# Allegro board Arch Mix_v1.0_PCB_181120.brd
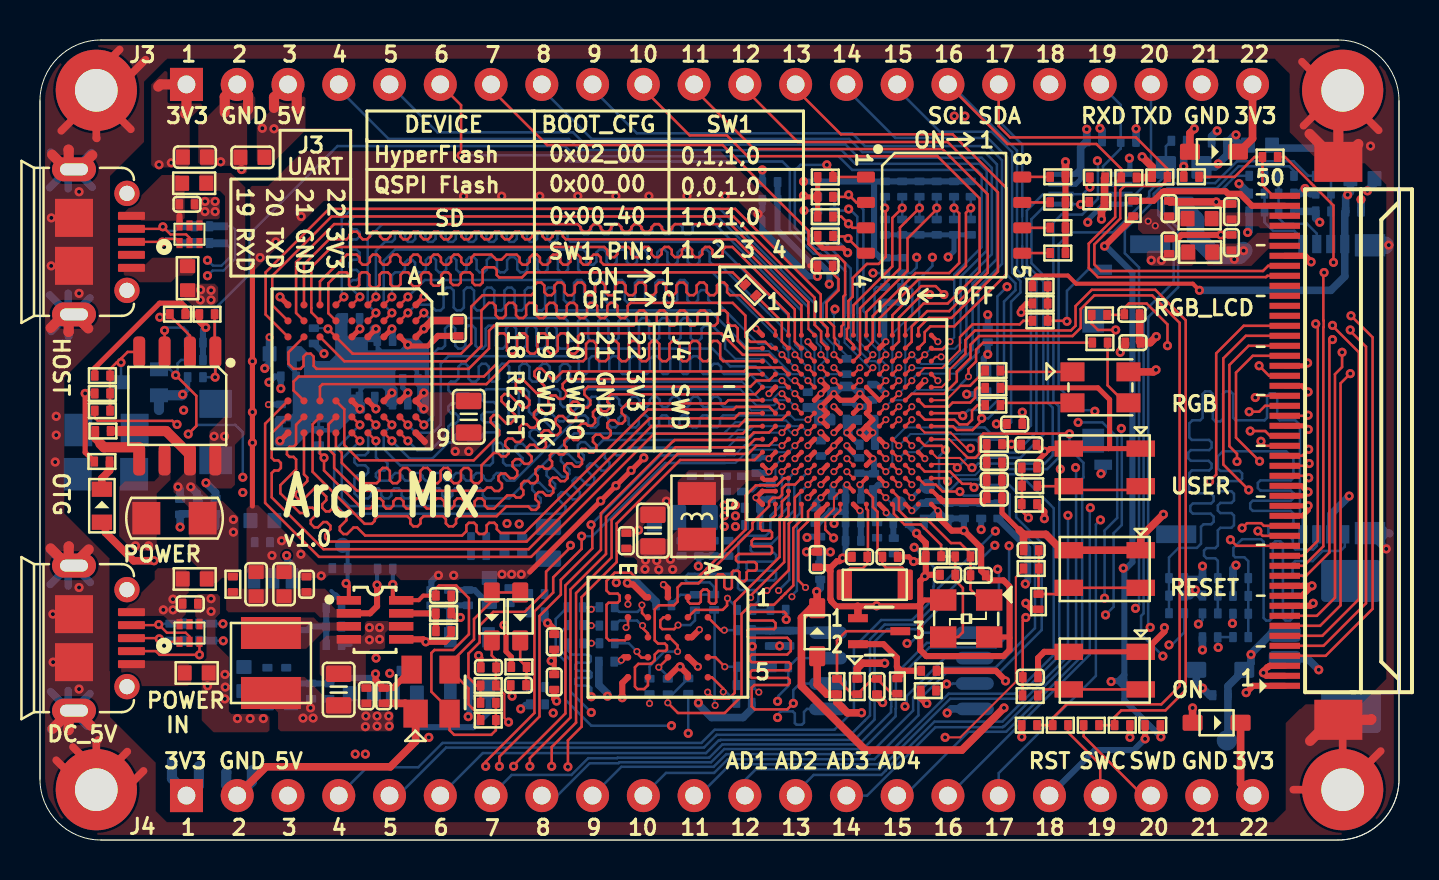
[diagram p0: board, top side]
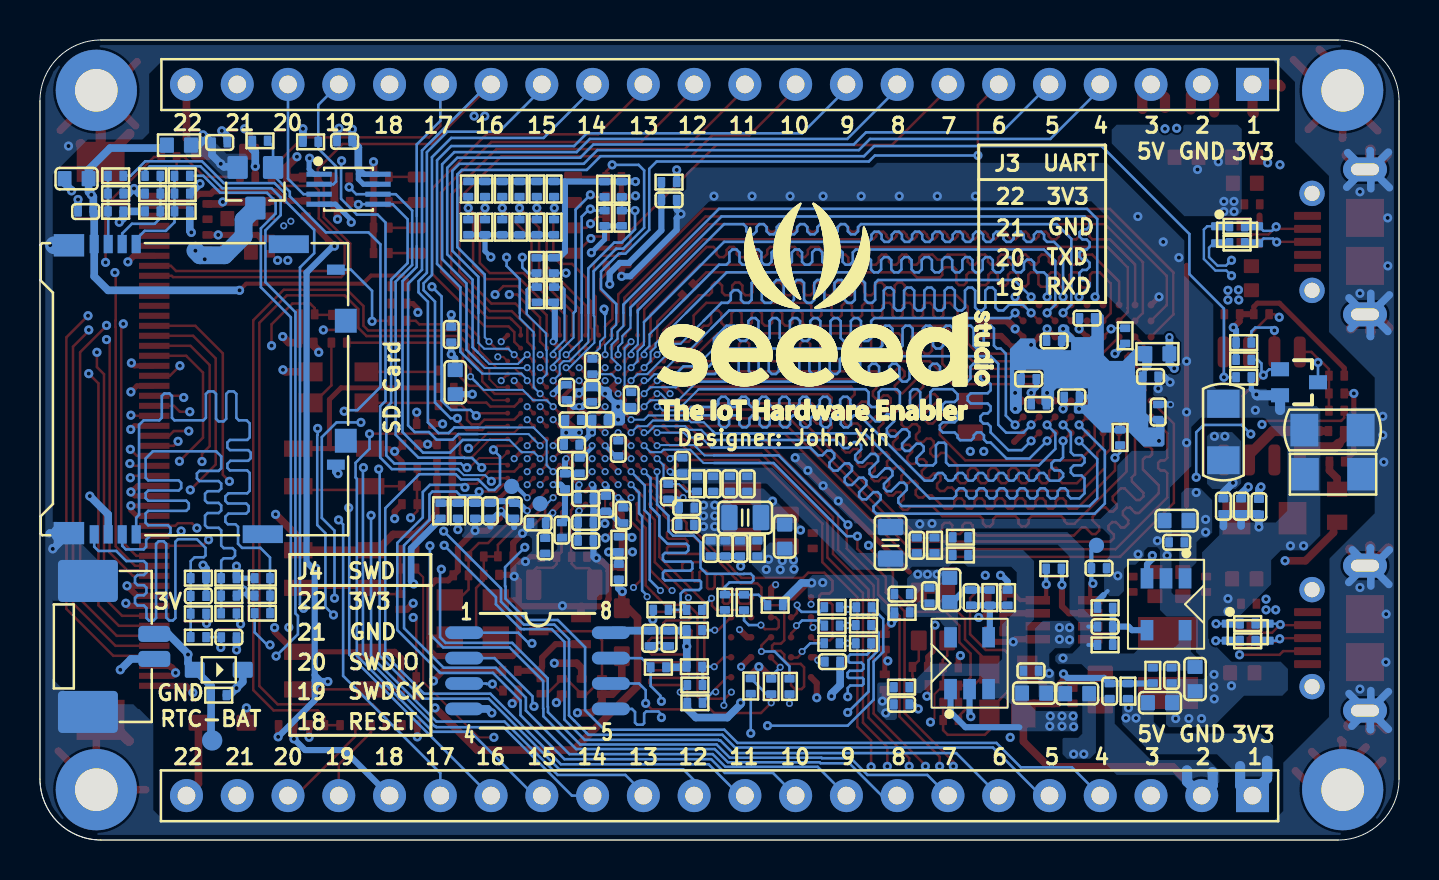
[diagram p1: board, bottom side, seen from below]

Outline 68 x 40 mm; copper layers: TOP, GND02, LYR03, PWR04, GND05, BOTTOM. Coordinates in mm from the lower left corner of the outline.
Outline path: 0,36.95 0,3.05 ; 0,36.95 arc(0.89,39.11) 3.05,40 ; 0,36.95 0,3.05 ; 0,3.05 arc(0.89,0.89) 3.05,0 ; 3.05,40 64.95,40 ; 3.05,40 64.95,40 ; 64.95,40 arc(67.11,39.11) 68,36.95 ; 3.05,0 64.95,0 ; 3.05,0 64.95,0 ; 64.95,0 arc(67.11,0.89) 68,3.05 ; 64.95,0 arc(67.11,0.89) 68,3.05 ; 68,36.95 68,3.05 ; 68,36.95 68,3.05

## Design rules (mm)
constraint set DEFAULT: min track width 0.102
net group DIFFPAIR7: nets USB_OTG_DN USB_OTG_DP
net group LCD_BL_PWM: nets LCD_BL_PWM N1454429
net group OTG2: nets USB_OTG2_DN USB_OTG2_DP
net group OTG3: nets USB_OTG1_DN USB_OTG1_DP
net group SEMC: nets SDRAM_CLK SEMC_DQS
net group ENET: nets ENET_CRS_DV ENET_MDC ENET_MDIO ENET_RXD0 ENET_RXD1 ENET_RXER ENET_TX_CLK ENET_TXD0 ENET_TXD1 ENET_TXEN
net group HF: nets HF_CLK HF_D0_A HF_D1_A HF_D2_A HF_D3_A HF_DQS HF_SS0
net group I2S: nets SAI1_MCLK SAI1_RX_BCLK SAI1_RX_SYNC SAI1_RXD/AD1_Y- SAI1_TX_BCLK/AD3_X- SAI1_TX_SYNC/AD4_X+ SAI1_TXD/AD2_Y+
net group LCD: nets LCD_CLK LCD_PWREN LCDIF_CLK LCDIF_D12 LCDIF_ENABLE LCDIF_HSYNC LCDIF_VSYNC
net group LCD_DATA: nets LCDIF_D0 LCDIF_D1 LCDIF_D2 LCDIF_D3 LCDIF_D4 LCDIF_D5 LCDIF_D6 LCDIF_D7 LCDIF_D8 LCDIF_D9 LCDIF_D10 LCDIF_D11 LCDIF_D13 LCDIF_D14 LCDIF_D15
net group POWER: nets VDD_USB_3V VDDA_1V1_CAP VDDA_2V5_CAP
net group QF: nets QF_CLK QF_D0_A QF_D1_A QF_D2_A QF_D3_A QF_SS0
net group SD: nets SD1_CLK SD1_CMD SD1_D0 SD1_D1 SD1_D2 SD1_D3 SD_CD SD_CD_SW SD_CLK SD_CMD SD_DAT0 SD_DAT1 SD_DAT2 SD_DAT3
net group SEMC_ADD: nets SEMC_CLK
net group SPI: nets FLEXSPI_CLK FLEXSPI_CLK_B FLEXSPI_D0_A FLEXSPI_D0_B FLEXSPI_D1_A FLEXSPI_D1_B FLEXSPI_D2_A FLEXSPI_D2_B FLEXSPI_D3_A FLEXSPI_D3_B FLEXSPI_DQS FLEXSPI_SS0

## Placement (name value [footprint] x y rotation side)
C1  22uF  [C1206]  6.73 16.09 180 top
C2  100nF  [C0402]  7.35 31.79 0 top
C3  100nF  [C0402]  7.52 11.81 0 top
C4  10uF  [C0603]  7.75 34.14 0 top
C5  10uF  [C0603]  10.63 34.13 180 top
C6  10uF  [C0603]  10.82 12.79 90 top
C7  10uF  [C0603]  12.21 12.79 90 top
C8  100nF  [C0402]  13.34 12.79 90 top
C9  22uF  [C0805]  14.95 7.52 90 top
C10  100nF  [C0402]  16.33 7.22 90 top
C11  100nF  [C0402]  17.2 7.22 270 top
C12  220nF  [C0402]  20.19 12.22 0 top
C13  100nF  [C0402]  20.94 25.59 90 top
C14  22uF  [C0805]  21.45 21.16 270 top
C15  1nF  [C0402]  22.44 8.63 180 top
C16  1uF  [C0402]  23.94 7.74 0 top
C17  4.7uF  [C0402]  25.73 9.91 270 top
C18  100nF  [C0402]  25.73 7.9 90 top
C19  220nF  [C0402]  29.34 14.96 90 top
C20  22uF  [C0805]  30.67 15.47 90 top
C21  1uF  [C0402]  38.89 14.02 270 top
C22  100nF  [C0402]  39.28 28.71 180 top
C23  24pF  [C0402]  41.01 14.16 180 top
C24  100nF  [C0402]  41.88 7.67 270 top
C25  24pF  [C0402]  42.53 14.16 0 top
C26  4.7pF  [C0402]  45.42 13.26 180 top
C27  4.7pF  [C0402]  46.94 13.23 0 top
C28  100nF  [C0402]  47.75 18.87 0 top
C29  1uF  [C0402]  47.75 17.98 0 top
C30  220nF  [C0402]  47.75 17.1 0 top
C31  100nF  [C0402]  48.77 20.8 0 top
C32  100nF  [C0402]  49.48 19.76 0 top
C33  1uF  [C0402]  49.5 18.62 0 top
C34  1uF  [C0402]  49.56 8.14 0 top
C35  1uF  [C0402]  49.59 14.49 180 top
C36  10pF  [C0402]  54.64 26.28 0 top
C37  4.7uF  [C0402]  54.69 24.87 0 top
C38  1uF  [C0402]  56.49 31.57 90 top
C39  1uF  [C0402]  56.49 29.69 90 top
C40  1uF  [C0402]  59.62 31.42 90 top
C41  1uF  [C0402]  59.62 29.87 90 top
C42  10uF  [C0603]  66.17 33.07 0 bottom
C43  100nF  [C0402]  65.71 31.42 0 bottom
C44  18pF  [C0402]  60.07 12.2 180 bottom
C45  100nF  [C0402]  59.01 34.88 180 bottom
C46  100nF  [C0402]  52.76 34.93 0 bottom
C47  100nF  [C0402]  47.42 25.27 270 bottom
C48  10uF  [C0603]  47.22 22.89 90 bottom
C49  4.7uF  [C0402]  46.23 16.46 270 bottom
C50  220nF  [C0402]  45.47 16.46 270 bottom
C51  100nF  [C0402]  44.27 16.46 270 bottom
C52  220nF  [C0402]  43.08 15.85 0 bottom
C53  4.7uF  [C0402]  42.72 14.71 270 bottom
C54  220nF  [C0402]  41.73 17.93 90 bottom
C55  4.7uF  [C0402]  41.88 15.5 270 bottom
C56  4.7uF  [C0402]  41.64 22.39 270 bottom
C57  220nF  [C0402]  41.4 19.76 180 bottom
C58  220nF  [C0402]  41.33 21.01 180 bottom
C59  100nF  [C0402]  41 18.72 270 bottom
C60  220nF  [C0402]  40.69 17.07 180 bottom
C61  4.7uF  [C0402]  40.69 15.88 180 bottom
C62  220nF  [C0402]  40.69 14.96 180 bottom
C63  220nF  [C0402]  40.37 22.29 270 bottom
C64  100nF  [C0402]  40.36 23.67 90 bottom
C65  220nF  [C0402]  39.97 21.02 0 bottom
C66  100nF  [C0402]  39.67 16.82 270 bottom
C67  100nF  [C0402]  39.07 19.58 270 bottom
C68  1uF  [C0402]  38.81 16.23 270 bottom
C69  4.7uF  [C0402]  38.42 22.01 90 bottom
C70  100nF  [C0402]  37.49 10.09 270 bottom
C71  220nF  [C0402]  36.56 17.42 270 bottom
C72  4.7uF  [C0402]  36.53 32.01 180 bottom
C73  1uF  [C0402]  36.53 10.09 270 bottom
C74  220nF  [C0402]  35.85 18.73 90 bottom
C75  220nF  [C0402]  35.66 15.75 0 bottom
C76  220nF  [C0402]  35.64 16.61 0 bottom
C77  220nF  [C0402]  34.44 14.58 270 bottom
C78  4.7uF  [C0402]  34.32 17.81 270 bottom
C79  220nF  [C0402]  33.71 14.58 270 bottom
C80  220nF  [C0402]  33.48 17.81 270 bottom
C81  220nF  [C0402]  32.97 14.58 270 bottom
C82  22uF  [C0805]  32.72 16.12 180 bottom
C83  220nF  [C0402]  32.61 17.81 270 bottom
C84  10uF  [C0603]  30.74 15.17 90 bottom
C85  100nF  [C0402]  28.35 8.92 180 bottom
C86  22uF  [C0805]  25.44 14.86 90 bottom
C87  100nF  [C0402]  24.89 6.78 180 bottom
C88  4.7uF  [C0402]  24.87 12.3 180 bottom
C89  100nF  [C0402]  24.13 14.73 90 bottom
C90  100nF  [C0402]  23.5 12.22 90 bottom
C91  10uF  [C0603]  22.48 12.5 90 bottom
C92  1nF  [C0402]  21.41 12.12 270 bottom
C93  100nF  [C0402]  18.53 23.05 180 bottom
C94  100nF  [C0402]  18.41 8.46 180 bottom
C95  10uF  [C0603]  18.26 7.35 180 bottom
C96  100nF  [C0402]  18.02 21.78 0 bottom
C97  100nF  [C0402]  17.26 24.95 0 bottom
C98  4.7uF  [C0402]  16.37 22.16 0 bottom
C99  10uF  [C0603]  16.1 7.32 0 bottom
C100  100nF  [C0402]  15.61 26.1 0 bottom
C101  1nF  [C0402]  15.01 13.59 180 bottom
C102  390pF  [C0402]  14.71 10.67 180 bottom
C103  100nF  [C0402]  14.48 7.44 270 bottom
C104  100nF  [C0402]  12.43 23.17 180 bottom
C105  10uF  [C0603]  11.96 6.86 180 bottom
C106  100nF  [C0402]  12.05 21.4 90 bottom
C107  100nF  [C0402]  11.38 8.23 270 bottom
C108  10uF  [C0603]  11.13 15.97 0 bottom
C109  100nF  [C0402]  11.13 14.89 0 bottom
C110  10uF  [C0603]  10.21 8.05 270 bottom
C111  22uF  [C1206]  8.79 20.4 90 bottom
C112  100nF  [C0402]  8.79 16.69 270 bottom
C113  100nF  [C0402]  7.9 16.69 270 bottom
C114  100nF  [C0402]  7.01 16.66 270 bottom
C115  1nF  [C1206]  3.33 20.5 0 bottom
C116  18pF  [C0402]  58.55 10.14 180 bottom
D1  PMEG3010CEJ  [SOD_323]  22.61 11.18 270 top
D2  PMEG3010CEJ  [SOD_323]  24.03 11.18 270 top
D3  PMEG3010CEJ  [SOD_323]  38.89 10.39 90 top
D4  ESDPSA0402V05  [D0402]  50.04 26.82 180 top
D5  PMEG3010CEJ  [SOD_323]  58.87 5.86 0 top
D6  PMEG3010CEJ  [SOD_323]  58.74 34.41 0 top
D7  ESDPSA0402V05  [D0402]  64.21 31.43 180 bottom
D8  ESDPSA0402V05  [D0402]  62.36 31.43 0 bottom
D9  ESDPSA0402V05  [D0402]  60.89 31.43 180 bottom
D10  ESDPSA0402V05  [D0402]  60.07 13.09 180 bottom
D11  PMEG3010CEJ  [SOD_323]  59.05 8.51 180 bottom
D12  ESDPSA0402V05  [D0402]  58.55 13.09 180 bottom
D13  ESDPSA0402V05  [D0402]  56.87 13.09 0 bottom
FB1  120R  [L0603]  7.72 32.84 180 top
FB2  120R  [L0603]  7.74 13.05 180 top
FB3  120R  [L0603]  58.02 31.07 0 top
FB4  120R  [L0603]  58.05 29.39 0 top
FB5  120R  [L0603]  61.04 34.74 0 bottom
FB6  120R  [L0603]  12.09 24.31 0 bottom
FB7  120R  [L0603]  7.84 8.35 180 top
FB8  120R  [L0603]  7.39 28.09 90 top
J1  USB-MC-001-05  [MICRO_USB_5_6P_SMD_0D65_AB]  1.7 29.91 270 top
J2  USB-MC-001-05  [MICRO_USB_5_6P_SMD_0D65_AB]  1.7 10.09 270 top
J3  Header 1x22 2.54mm  [HEADER22P_2D54_DIP]  34 37.78 270 bottom
J4  Header 1x22 2.54mm  [HEADER22P_2D54_DIP]  34 2.22 270 bottom
J5  FPC 50Pin Bottom Contact  [FPC50_2P5_T]  62.28 32.21 180 top
J6  Header 1x2 1.25mm  [JST2P_1D25_7_55X3_9MM]  62.28 9.68 270 bottom
J7  SCHA5B0200  [SD-MICRO-SCHA5B0300]  63.19 22.54 270 bottom
L1  1uH  [L4X4MM]  11.56 8.85 270 top
L2  4.7uH  [L1008]  32.87 16.18 270 top
L3  90R  [L2012]  8.1 30.26 180 bottom
L4  90R  [L2012]  7.57 10.39 180 bottom
LED1  Green  [LED0603]  3.1 16.71 90 top
LED2  RGB  [LED350X280-4]  53.06 22.63 0 top
MTG1  MHOLE  [MTGH160C80D_PL]  2.82 37.48 0 top
MTG2  MHOLE  [MTGH160C80D_PL]  2.82 2.52 0 top
MTG3  MHOLE  [MTGH160C80D_PL]  65.18 37.48 0 top
MTG4  MHOLE  [MTGH160C80D_PL]  65.18 2.52 0 top
NOREF  -  []  0 40.59 0 top
NOREF#2  -  []  4.24 0 90 top
NOREF#3  -  []  5.58 13.01 0 top
NOREF#4  -  []  29.38 29.3 180 bottom
Q1  DMP2035U-7  [SOT23]  57.23 32.61 0 bottom
Q2  BSS138W  [SOT-323-3]  5 22.89 270 bottom
R1  1K  [R0402]  3.1 18.92 0 top
R2  10K  [R0402]  3.12 23.22 0 top
R3  10K  [R0402]  3.12 22.33 180 top
R4  0R  [R0402]  3.12 21.46 0 top
R5  0R  [R0402]  3.15 20.45 0 top
R6  10K  [R0402]  6.88 26.29 180 top
R7  10K  [R0402]  8.36 26.29 0 top
R8  0R  [R0402]  9.65 12.79 270 top
R9  40.2K  [R0402]  20.19 11.33 0 top
R10  180K  [R0402]  20.19 10.44 180 top
R11  0R  [R0402]  22.43 7.72 0 top
R12  10K  [R0402]  22.43 6.86 0 top
R13  0R  [R0402]  22.43 6 0 top
R14  1M  [R0402]  23.96 8.65 180 top
R15  33R  [R0402]  35.55 27.49 135 top
R16  10K  [R0402]  39.29 33.15 0 top
R17  10K  [R0402]  39.29 32.16 0 top
R18  10K  [R0402]  39.29 31.17 0 top
R19  10K  [R0402]  39.29 30.2 0 top
R20  1.5K  [R0402]  39.88 7.67 90 top
R21  1.5K  [R0402]  40.89 7.67 270 top
R22  0R  [R0402]  42.9 7.7 90 top
R23  10K  [R0402]  44.45 7.47 0 top
R24  1K  [R0402]  44.48 8.46 0 top
R25  2.2M  [R0402]  44.7 14.18 180 top
R26  1M  [R0402]  46.18 14.17 0 top
R27  1.5K  [R0402]  47.68 23.47 180 top
R28  10K  [R0402]  47.68 22.61 0 top
R29  4.7K  [R0402]  47.68 21.74 180 top
R30  0R  [R0402]  47.75 19.79 180 top
R31  100K  [R0402]  49.5 16.79 180 top
R32  100K  [R0402]  49.5 5.74 180 top
R33  100R  [R0402]  49.52 17.71 180 top
R34  100R  [R0402]  49.54 7.22 180 top
R35  100R  [R0402]  49.59 13.57 180 top
R36  100R  [R0402]  49.96 11.91 270 top
R37  10K  [R0402]  50.04 27.69 0 top
R38  33R  [R0402]  50.04 25.96 0 top
R39  1K  [R0402]  50.93 33.16 180 top
R40  1K  [R0402]  50.93 31.89 180 top
R41  1K  [R0402]  50.93 30.62 180 top
R42  1K  [R0402]  50.93 29.35 180 top
R43  33R  [R0402]  51.05 5.74 0 top
R44  33R  [R0402]  52.6 5.74 180 top
R45  10K  [R0402]  52.88 31.9 180 top
R46  10K  [R0402]  52.91 33.13 180 top
R47  33R  [R0402]  53.01 26.26 0 top
R48  1.5K  [R0402]  53.04 24.87 180 top
R49  100K  [R0402]  54.15 5.74 180 top
R50  4.7K  [R0402]  54.48 33.12 180 top
R51  0R  [R0402]  55.68 5.74 180 top
R52  4.7K  [R0402]  56.03 33.15 0 top
R53  1K  [R0402]  57.61 33.16 180 top
R54  0R  [R0402]  54.7 31.58 90 top
R55  0R  [R0402]  61.55 34.15 180 top
R56  33R  [R0402]  64.21 33.21 0 bottom
R57  10K  [R0402]  64.21 32.32 0 bottom
R58  33R  [R0402]  62.36 33.21 180 bottom
R59  10K  [R0402]  62.36 32.32 180 bottom
R60  33R  [R0402]  60.89 33.21 0 bottom
R61  10K  [R0402]  60.89 32.32 0 bottom
R62  10K  [R0402]  60.07 11.31 0 bottom
R63  33R  [R0402]  60.07 10.15 0 bottom
R64  1K  [R0402]  59.05 7.24 180 bottom
R65  10K  [R0402]  58.55 12.22 0 bottom
R66  33R  [R0402]  58.55 11.33 0 bottom
R67  10K  [R0402]  56.99 34.96 0 bottom
R68  10K  [R0402]  56.87 12.22 180 bottom
R69  33R  [R0402]  56.87 11.34 180 bottom
R70  100K  [R0402]  54.46 34.91 0 bottom
R71  0R  [R0402]  47.96 16.46 90 bottom
R72  0R  [R0402]  47.09 16.46 90 bottom
R73  1K  [R0402]  46.57 32.55 270 bottom
R74  10K  [R0402]  46.57 30.64 90 bottom
R75  1K  [R0402]  45.73 32.55 270 bottom
R76  10K  [R0402]  45.73 30.64 90 bottom
R77  1K  [R0402]  44.87 32.55 270 bottom
R78  10K  [R0402]  44.87 30.64 90 bottom
R79  1K  [R0402]  44.01 32.55 270 bottom
R80  10K  [R0402]  44.01 30.64 90 bottom
R81  1K  [R0402]  43.15 28.73 270 bottom
R82  1K  [R0402]  43.14 32.55 270 bottom
R83  10K  [R0402]  43.14 30.64 90 bottom
R84  10K  [R0402]  43.14 27.26 90 bottom
R85  1K  [R0402]  42.29 28.73 270 bottom
R86  1K  [R0402]  42.28 32.55 270 bottom
R87  10K  [R0402]  42.28 30.64 90 bottom
R88  10K  [R0402]  42.28 27.26 90 bottom
R89  1K  [R0402]  39.75 32.54 270 bottom
R90  10K  [R0402]  39.75 31.09 90 bottom
R91  100K  [R0402]  39.04 14.78 90 bottom
R92  100R  [R0402]  39.04 13.41 90 bottom
R93  1K  [R0402]  38.89 32.54 270 bottom
R94  10K  [R0402]  38.89 31.09 90 bottom
R95  10K  [R0402]  37.06 8.64 0 bottom
R96  33R  [R0402]  36.93 11.51 0 bottom
R97  0R  [R0402]  36.53 32.89 0 bottom
R98  0R  [R0402]  35.27 11.5 180 bottom
R99  10K  [R0402]  35.26 10.49 180 bottom
R100  10K  [R0402]  35.26 8.66 180 bottom
R101  0R  [R0402]  35.23 7.75 180 bottom
R102  10K  [R0402]  35.23 6.86 180 bottom
R103  30K  [R0402]  35.13 17.81 90 bottom
R104  0R  [R0402]  33.73 11.89 270 bottom
R105  0R  [R0402]  32.77 11.88 270 bottom
R106  0R  [R0402]  32.44 7.7 90 bottom
R107  0R  [R0402]  32.11 14.58 270 bottom
R108  0R  [R0402]  31.41 7.68 90 bottom
R109  10K  [R0402]  31.22 11.74 0 bottom
R110  0R  [R0402]  30.5 7.68 90 bottom
R111  0R  [R0402]  28.38 9.84 0 bottom
R112  0R  [R0402]  28.37 11.64 0 bottom
R113  0R  [R0402]  28.37 10.72 0 bottom
R114  0R  [R0402]  26.8 10.75 0 bottom
R115  0R  [R0402]  26.8 9.83 0 bottom
R116  0R  [R0402]  26.77 11.63 0 bottom
R117  0R  [R0402]  24.89 7.65 0 bottom
R118  0R  [R0402]  24.87 11.38 0 bottom
R119  3.3K  [R0402]  23.24 14.73 90 bottom
R120  0R  [R0402]  21.95 15.14 0 bottom
R121  0R  [R0402]  21.95 14.25 0 bottom
R122  22.6K  [R0402]  20.47 12.12 270 bottom
R123  18K  [R0402]  19.58 12.12 90 bottom
R124  100K  [R0402]  17.27 13.57 0 bottom
R125  18K  [R0402]  14.71 11.61 0 bottom
R126  56.2K  [R0402]  14.71 9.76 180 bottom
R127  100K  [R0402]  13.96 20.13 270 bottom
R128  0R  [R0402]  13.56 7.44 90 bottom
R129  100K  [R0402]  13.7 25.21 270 bottom
R130  0R  [R0402]  12.32 8.23 270 bottom
R131  0R  [R0402]  8.1 30.68 180 bottom
R132  0R  [R0402]  8.1 29.85 180 bottom
R133  10K  [R0402]  7.77 24.87 180 bottom
R134  10K  [R0402]  7.77 24 180 bottom
R135  10K  [R0402]  7.77 23.14 180 bottom
R136  0R  [R0402]  7.57 10.82 180 bottom
R137  0R  [R0402]  7.57 9.96 180 bottom
R138  0R  [R1206]  3.3 18.29 0 bottom
SW1  DIP Switches  [SW8P_1D27_6_21X6_2X2_3MM]  45.24 31.24 0 top
SW2  Tactile Switch  [SW_4P]  53.28 18.63 180 top
SW3  Tactile Switch  [SW_4P]  53.28 13.55 180 top
SW4  Tactile Switch  [SW_4P]  53.28 8.47 180 top
TP1  TP_30MIL  [TESTPOINT_30]  44.4 17.68 180 bottom
TP2  TP_30MIL  [TESTPOINT_30]  42.98 16.82 180 bottom
TP3  TP_30MIL  [TESTPOINT_30]  15.14 14.73 180 bottom
TP4  TP_40MIL  [TP40C_SMD]  59.39 4.98 180 bottom
U1  MIC2026-1YM-TR  [SOIC8_1D27_4_9X3_9MM]  6.87 21.7 180 top
U2  TPD4S012DRYR  [U_6_DRY]  7.48 30.29 0 top
U3  TPD4S012DRYR  [U_6_DRY]  7.48 10.35 0 top
U4  IS42S16160J-6BLI  [VFBGA54_8X8]  15.61 23.56 270 top
U5  MP2161GJ  [TSOT23_8_0D65_2X1MM]  16.76 11.01 0 top
U6  UM805RE  [SOT_143]  19.55 7.42 0 top
U7  S26KS512SDPBHI02  [PBGA24_1_6X8MM]  31.42 10.14 270 top
U8  MIMXRT1052CVL5B  [BGA196_0P65_10X10MM]  40.37 21.02 0 top
U9  MIC803-29D3VC3-TR  [SC-70-3]  41.99 10.44 270 top
U10  SN74LVC2G241DCUR  [U_8_DCU]  52.56 32.54 270 bottom
U11  IS25WP064A-JBLE  [SO8-25X75-200]  43.1 8.46 270 bottom
U12  AP2127K-ADJTRG1  [SOT23-5]  21.49 8.84 180 bottom
U13  AP2127K-ADJTRG1  [SOT23-5]  11.66 11.79 0 bottom
X1  32.768kHz 12.5pF  [X2_SMD_3_2X1_5MM]  41.77 12.76 180 top
X2  24MHz 9pF  [X4-SMD-3_2X2_5X1_0MM]  46.34 11.08 180 top

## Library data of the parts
C1-C116 = CC
D1-D3 D5 D6 D11 = D
D4 D7-D10 D12 D13 = DIODE TVS BI-DIR
FB1-FB8 = FB
J1 J2 = MicroUSB_5+6P
J3 J4 = Header 1x22
J5 = FPC50 For Emb
J6 = Header_2+2P
J7 = MicroSD Card_8P: Tolerance: X; User Part Number: X
L1 L2 = L
L3 L4 = CL
LED1 = Single LED
LED2 = RGB_LED
MTG1-MTG4 = MHOLE
Q1 = PMOS_123
Q2 = NMOS_123: User Part Number: *
R1-R3 R5-R18 R20-R75 R77-R87 R91-R138 = R
R4 R19 R76 R88-R90 = R: signal model: RES_0402_CC_DISCRETE_0.45_MM_47_0
SW1 = DIP Switches_4CH
SW2-SW4 = Tactile Switch_4P
TP1-TP3 = T POINT R: User Part Number: USERPART#; Tolerance: TOLERANCE
TP4 = T POINT R
U1 = MIC2026
U2 U3 = TPD4S012
U4 = SDRAM_BGA54
U5 = MP2161
U6 = UM805_4P
U7 = HyperFlash_FBGA-24
U8 = MIMXRT1052_BGA-196
U9 = MIC803
U10 = SN74LVC2G241
U11 = QPI_8P
U12 U13 = LDO_5P_FB
X1 = XTAL_2P
X2 = XTAL_4P

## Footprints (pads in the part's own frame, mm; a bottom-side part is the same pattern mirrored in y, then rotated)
BGA196_0P65_10X10MM
  round 0.254 smd: A1(-4.225,4.225) A2(-3.575,4.225) A3(-2.925,4.225) A4(-2.275,4.225) A5(-1.625,4.225) A6(-0.975,4.225) A7(-0.325,4.225) A8(0.325,4.225) A9(0.975,4.225) A10(1.625,4.225) A11(2.275,4.225) A12(2.925,4.225) A13(3.575,4.225) A14(4.225,4.225) B1(-4.225,3.575) B2(-3.575,3.575) B3(-2.925,3.575) B4(-2.275,3.575) B5(-1.625,3.575) B6(-0.975,3.575) B7(-0.325,3.575) B8(0.325,3.575) B9(0.975,3.575) B10(1.625,3.575) B11(2.275,3.575) B12(2.925,3.575) B13(3.575,3.575) B14(4.225,3.575) C1(-4.225,2.925) C2(-3.575,2.925) C3(-2.925,2.925) C4(-2.275,2.925) C5(-1.625,2.925) C6(-0.975,2.925) C7(-0.325,2.925) C8(0.325,2.925) C9(0.975,2.925) C10(1.625,2.925) C11(2.275,2.925) C12(2.925,2.925) C13(3.575,2.925) C14(4.225,2.925) D1(-4.225,2.275) D2(-3.575,2.275) D3(-2.925,2.275) D4(-2.275,2.275) D5(-1.625,2.275) D6(-0.975,2.275) D7(-0.325,2.275) D8(0.325,2.275) D9(0.975,2.275) D10(1.625,2.275) D11(2.275,2.275) D12(2.925,2.275) D13(3.575,2.275) D14(4.225,2.275) E1(-4.225,1.625) E2(-3.575,1.625) E3(-2.925,1.625) E4(-2.275,1.625) E5(-1.625,1.625) E6(-0.975,1.625) E7(-0.325,1.625) E8(0.325,1.625) E9(0.975,1.625) E10(1.625,1.625) E11(2.275,1.625) E12(2.925,1.625) E13(3.575,1.625) E14(4.225,1.625) F1(-4.225,0.975) F2(-3.575,0.975) F3(-2.925,0.975) F4(-2.275,0.975) F5(-1.625,0.975) F6(-0.975,0.975) F7(-0.325,0.975) F8(0.325,0.975) F9(0.975,0.975) F10(1.625,0.975) F11(2.275,0.975) F12(2.925,0.975) F13(3.575,0.975) F14(4.225,0.975) G1(-4.225,0.325) G2(-3.575,0.325) G3(-2.925,0.325) G4(-2.275,0.325) G5(-1.625,0.325) G6(-0.975,0.325) G7(-0.325,0.325) G8(0.325,0.325) G9(0.975,0.325) G10(1.625,0.325) G11(2.275,0.325) G12(2.925,0.325) G13(3.575,0.325) G14(4.225,0.325) H1(-4.225,-0.325) H2(-3.575,-0.325) H3(-2.925,-0.325) H4(-2.275,-0.325) H5(-1.625,-0.325) H6(-0.975,-0.325) H7(-0.325,-0.325) H8(0.325,-0.325) H9(0.975,-0.325) H10(1.625,-0.325) H11(2.275,-0.325) H12(2.925,-0.325) H13(3.575,-0.325) H14(4.225,-0.325) J1(-4.225,-0.975) J2(-3.575,-0.975) J3(-2.925,-0.975) J4(-2.275,-0.975) J5(-1.625,-0.975) J6(-0.975,-0.975) J7(-0.325,-0.975) J8(0.325,-0.975) J9(0.975,-0.975) J10(1.625,-0.975) J11(2.275,-0.975) J12(2.925,-0.975) J13(3.575,-0.975) J14(4.225,-0.975) K1(-4.225,-1.625) K2(-3.575,-1.625) K3(-2.925,-1.625) K4(-2.275,-1.625) K5(-1.625,-1.625) K6(-0.975,-1.625) K7(-0.325,-1.625) K8(0.325,-1.625) K9(0.975,-1.625) K10(1.625,-1.625) K11(2.275,-1.625) K12(2.925,-1.625) K13(3.575,-1.625) K14(4.225,-1.625) L1(-4.225,-2.275) L2(-3.575,-2.275) L3(-2.925,-2.275) L4(-2.275,-2.275) L5(-1.625,-2.275) L6(-0.975,-2.275) L7(-0.325,-2.275) L8(0.325,-2.275) L9(0.975,-2.275) L10(1.625,-2.275) L11(2.275,-2.275) L12(2.925,-2.275) L13(3.575,-2.275) L14(4.225,-2.275) M1(-4.225,-2.925) M2(-3.575,-2.925) M3(-2.925,-2.925) M4(-2.275,-2.925) M5(-1.625,-2.925) M6(-0.975,-2.925) M7(-0.325,-2.925) M8(0.325,-2.925) M9(0.975,-2.925) M10(1.625,-2.925) M11(2.275,-2.925) M12(2.925,-2.925) M13(3.575,-2.925) M14(4.225,-2.925) N1(-4.225,-3.575) N2(-3.575,-3.575) N3(-2.925,-3.575) N4(-2.275,-3.575) N5(-1.625,-3.575) N6(-0.975,-3.575) N7(-0.325,-3.575) N8(0.325,-3.575) N9(0.975,-3.575) N10(1.625,-3.575) N11(2.275,-3.575) N12(2.925,-3.575) N13(3.575,-3.575) N14(4.225,-3.575) P1(-4.225,-4.225) P2(-3.575,-4.225) P3(-2.925,-4.225) P4(-2.275,-4.225) P5(-1.625,-4.225) P6(-0.975,-4.225) P7(-0.325,-4.225) P8(0.325,-4.225) P9(0.975,-4.225) P10(1.625,-4.225) P11(2.275,-4.225) P12(2.925,-4.225) P13(3.575,-4.225) P14(4.225,-4.225)
C0402
  rrect 0.385x0.508 smd: 1(-0.383,0) 2(0.383,0)
C0603
  rrect 0.696x0.762 smd: 1(-0.602,0) 2(0.602,0)
C0805
  rrect 0.819x1.27 smd: 1(-0.79,0) 2(0.79,0)
C1206
  rect 1.397x1.626 smd: 1(-1.41,0) 2(1.41,0)
D0402
  rrect 0.385x0.508 smd: 1(-0.383,0) 2(0.383,0)
FPC50_2P5_T
  rect 1.524x0.305 smd: 1(0,24.5) 2(0,24) 3(0,23.5) 4(0,23) 5(0,22.5) 6(0,22) 7(0,21.5) 8(0,21) 9(0,20.5) 10(0,20) 11(0,19.5) 12(0,19) 13(0,18.5) 14(0,18) 15(0,17.5) 16(0,17) 17(0,16.5) 18(0,16) 19(0,15.5) 20(0,15) 21(0,14.5) 22(0,14) 23(0,13.5) 24(0,13) 25(0,12.5) 26(0,12) 27(0,11.5) 28(0,11) 29(0,10.5) 30(0,10) 31(0,9.5) 32(0,9) 33(0,8.5) 34(0,8) 35(0,7.5) 36(0,7) 37(0,6.5) 38(0,6) 39(0,5.5) 40(0,5) 41(0,4.5) 42(0,4) 43(0,3.5) 44(0,3) 45(0,2.5) 46(0,2) 47(0,1.5) 48(0,1) 49(0,0.5) 50(0,0)
  rect 2.4x2 smd: 51(-2.68,26.2) 52(-2.68,-1.7)
HEADER22P_2D54_DIP
  rect 1.651x1.651 hole 0.889: 1(0,26.67)
  round 1.651 hole 0.889: 2(0,24.13) 3(0,21.59) 4(0,19.05) 5(0,16.51) 6(0,13.97) 7(0,11.43) 8(0,8.89) 9(0,6.35) 10(0,3.81) 11(0,1.27) 12(0,-1.27) 13(0,-3.81) 14(0,-6.35) 15(0,-8.89) 16(0,-11.43) 17(0,-13.97) 18(0,-16.51) 19(0,-19.05) 20(0,-21.59) 21(0,-24.13) 22(0,-26.67)
JST2P_1D25_7_55X3_9MM
  rrect 0.8x1.6 smd: 1(-0.625,0) 2(0.625,0)
  rrect 2.1x3 smd: 3(-3.275,-3.319) 4(3.275,-3.319)
L4X4MM
  rect 1.6x3 smd: 1(-1.5,0) 2(1.5,0)
L0603
  rrect 0.696x0.762 smd: 1(-0.602,0) 2(0.602,0)
L1008
  rect 1.143x1.905 smd: 1(-1.143,0) 2(1.143,0)
L2012
  rrect 0.75x0.4 smd: 1(-0.925,0.425) 2(0.925,0.425) 3(0.925,-0.425) 4(-0.925,-0.425)
LED350X280-4
  rect 1.2x0.95 smd: 1(-1.4,0.775) 2(1.4,0.775) 3(1.4,-0.775) 4(-1.4,-0.775)
LED0603
  rect 0.762x1.016 smd: 1(-0.826,0) 2(0.826,0)
MICRO_USB_5_6P_SMD_0D65_AB
  rrect 0.4x1.35 smd: 1(-1.3,2.875) 2(-0.65,2.875) 3(0,2.875) 4(0.65,2.875) 5(1.3,2.875)
  round 1.27 hole 0.762: 6(-2.425,2.65) 7(2.425,2.65)
  oval 1.2x2.2 hole 0.6x1.4: 8(-3.625,0) 9(3.625,0)
  rect 1.9x1.9 smd: 10(-1.2,0) 11(1.2,0)
MTGH160C80D_PL
  round 4.064 hole 2.134: 1(0,0)
PBGA24_1_6X8MM
  round 0.33 smd: A2(-1,2) A3(0,2) A4(1,2) A5(2,2) B1(-2,1) B2(-1,1) B3(0,1) B4(1,1) B5(2,1) C1(-2,0) C2(-1,0) C3(0,0) C4(1,0) C5(2,0) D1(-2,-1) D2(-1,-1) D3(0,-1) D4(1,-1) D5(2,-1) E1(-2,-2) E2(-1,-2) E3(0,-2) E4(1,-2) E5(2,-2)
R0402
  rrect 0.385x0.508 smd: 1(-0.383,0) 2(0.383,0)
R1206
  rect 1.397x1.626 smd: 1(-1.41,0) 2(1.41,0)
SC-70-3
  rect 0.406x0.991 smd: 1(-0.65,-1.06) 2(0.65,-1.06) 3(0,1.06)
SD-MICRO-SCHA5B0300
  rect 0.914x0.457 smd: 1(-7.257,0) 2(-7.257,-0.7) 3(-7.257,-1.4) 4(-7.257,-2.1) 5(7.257,-2.1) 6(7.257,-1.4) 7(7.257,-0.7) 8(7.257,0)
  rect 0.508x0.889 smd: 9(3.775,9.989) 10(-5.975,9.989)
  rect 0.889x2.007 smd: 11(-7.25,7.635) 12(7.25,6.335)
  rect 1.118x1.524 smd: 13(-7.196,-3.365) 14(7.196,-3.365)
  rect 1.194x1.092 smd: 15(-3.425,10.488) 16(2.575,10.488)
SO8-25X75-200
  oval 0.635x1.905 smd: 1(-1.905,-3.67) 2(-0.635,-3.67) 3(0.635,-3.67) 4(1.905,-3.67) 5(1.905,3.67) 6(0.635,3.67) 7(-0.635,3.67) 8(-1.905,3.67)
SOD_323
  rrect 1x0.8 smd: 1(-1.2,0) 2(1.2,0)
SOIC8_1D27_4_9X3_9MM
  rrect 0.6x1.55 smd: 1(-1.905,-2.7) 2(-0.635,-2.7) 3(0.635,-2.7) 4(1.905,-2.7) 5(1.905,2.7) 6(0.635,2.7) 7(-0.635,2.7) 8(-1.905,2.7)
SOT23
  rrect 1.016x1.143 smd: 1(-0.889,-1.016) 2(0.889,-1.016) 3(0,1.016)
SOT23-5
  rect 0.635x1.016 smd: 1(-0.953,-1.295) 2(0,-1.295) 3(0.953,-1.295) 4(0.953,1.295) 5(-0.953,1.295)
SOT-323-3
  rect 0.7x0.9 smd: 1(-0.65,-0.95) 2(0.65,-0.95) 3(0,0.95)
SOT_143
  rect 1.219x1.397 smd: 1(-0.75,-1.1)
  rect 1.016x1.397 smd: 2(0.95,-1.1) 3(0.95,1.1) 4(-0.95,1.1)
SW8P_1D27_6_21X6_2X2_3MM
  rrect 0.9x0.55 smd: 1(-3.91,1.905) 2(-3.91,0.635) 3(-3.91,-0.635) 4(-3.91,-1.905) 5(3.91,-1.905) 6(3.91,-0.635) 7(3.91,0.635) 8(3.91,1.905)
SW_4P
  rect 1.422x0.813 smd: 1(-1.8,-0.94) 2(-1.8,0.94) 3(1.8,-0.94) 4(1.8,0.94)
TESTPOINT_30
  round 0.762 smd: 1(0,0)
TP40C_SMD
  round 1.016 smd: 1(0,0)
TSOT23_8_0D65_2X1MM
  rect 1.219x0.432 smd: 1(-1.31,0.975) 2(-1.31,0.325) 3(-1.31,-0.325) 4(-1.31,-0.975) 5(1.31,-0.975) 6(1.31,-0.325) 7(1.31,0.325) 8(1.31,0.975)
U_6_DRY
  rect 0.305x0.508 smd: 1(-0.5,-0.439) 2(0,-0.439) 3(0.5,-0.439) 4(0.5,0.439) 5(0,0.439) 6(-0.5,0.439)
U_8_DCU
  rect 0.254x1.27 smd: 1(-0.749,-1.473) 2(-0.249,-1.473) 3(0.249,-1.473) 4(0.749,-1.473) 5(0.749,1.473) 6(0.249,1.473) 7(-0.249,1.473) 8(-0.749,1.473)
VFBGA54_8X8
  round 0.356 smd: A1(-3.2,3.2) A2(-2.4,3.2) A3(-1.6,3.2) A7(1.6,3.2) A8(2.4,3.2) A9(3.2,3.2) B1(-3.2,2.4) B2(-2.4,2.4) B3(-1.6,2.4) B7(1.6,2.4) B8(2.4,2.4) B9(3.2,2.4) C1(-3.2,1.6) C2(-2.4,1.6) C3(-1.6,1.6) C7(1.6,1.6) C8(2.4,1.6) C9(3.2,1.6) D1(-3.2,0.8) D2(-2.4,0.8) D3(-1.6,0.8) D7(1.6,0.8) D8(2.4,0.8) D9(3.2,0.8) E1(-3.2,0) E2(-2.4,0) E3(-1.6,0) E7(1.6,0) E8(2.4,0) E9(3.2,0) F1(-3.2,-0.8) F2(-2.4,-0.8) F3(-1.6,-0.8) F7(1.6,-0.8) F8(2.4,-0.8) F9(3.2,-0.8) G1(-3.2,-1.6) G2(-2.4,-1.6) G3(-1.6,-1.6) G7(1.6,-1.6) G8(2.4,-1.6) G9(3.2,-1.6) H1(-3.2,-2.4) H2(-2.4,-2.4) H3(-1.6,-2.4) H7(1.6,-2.4) H8(2.4,-2.4) H9(3.2,-2.4) J1(-3.2,-3.2) J2(-2.4,-3.2) J3(-1.6,-3.2) J7(1.6,-3.2) J8(2.4,-3.2) J9(3.2,-3.2)
X2_SMD_3_2X1_5MM
  rrect 0.762x1.524 smd: 1(-1.524,0) 2(1.524,0)
X4-SMD-3_2X2_5X1_0MM
  rect 1.321x1.067 smd: 1(-1.15,-0.925) 2(1.15,-0.925) 3(1.15,0.925) 4(-1.15,0.925)

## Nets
3V3_LCD: C41.1 FB4.2 J5.45 J5.46 Q1.3
3V3_SD: C42.1 C43.1 FB5.2 J7.4 R37.1 R57.1 R59.1 R61.1 R62.1 R65.1 R68.1
5V_HOST: C2.1 FB1.2 J1.1(VBUS) U2.6(VBUS)
5V_LCD: C40.1 FB3.2 J5.47 J5.48
5V_OTG: C3.1 C5.1 C99.1 FB2.2 J2.1(VBUS) J3.3 J4.3 U3.6(VBUS)
5V_USB_HOST: C21.1 C111.1 C112.1 FB1.1 U1.8 U8.P6
5V_USB_OTG: C1.1 C38.1 C68.1 C108.1 C109.1 C113.1 C114.1 FB2.1 FB3.1 R5.2 R8.1 U1.7 U8.N6 U13.1 U13.3(S\H\D\N\)
GND: C1.2 C2.2 C3.2 C4.2 C5.2 C6.2 C7.2 C8.2 C9.2 C10.2 C11.2 C12.2 C13.2 C14.2 C15.2 C17.2 C18.2 C19.2 C20.2 C21.2 C22.2 C23.2 C24.2 C25.2 C26.2 C27.2 C28.2 C29.2 C30.2 C31.2 C32.2 C33.2 C34.2 C35.2 C36.2 C37.2 C38.2 C39.2 C40.2 C41.2 C42.2 C43.2 C44.2 C45.2 C46.2 C47.2 C48.2 C49.2 C50.2 C51.2 C52.2 C53.2 C54.2 C55.2 C56.2 C57.2 C58.2 C59.2 C60.2 C61.2 C62.2 C63.2 C64.2 C65.2 C66.2 C67.2 C68.2 C69.2 C70.2 C71.2 C72.2 C73.2 C74.2 C75.2 C76.2 C77.2 C78.2 C79.2 C80.2 C81.2 C82.2 C83.2 C84.2 C85.2 C86.2 C87.2 C88.2 C89.2 C90.2 C91.2 C93.2 C94.2 C95.2 C96.2 C97.2 C98.2 C99.2 C100.2 C101.2 C103.2 C104.2 C105.2 C106.2 C107.2 C108.2 C109.2 C110.2 C111.2 C112.2 C113.2 C114.2 C115.2 C116.2 D4.2 D7.2 D8.2 D9.2 D10.2 D12.2 D13.2 FB7.1 FB8.1 J3.2 J3.21 J4.2 J4.21 J5.1 J5.2 J5.3 J5.9 J5.10 J5.11 J5.18 J5.19 J5.20 J5.21 J5.27 J5.31 J5.33 J5.44 J6.2 J7.6(VSS) J7.9 Q2.2(S) R1.1 R3.2 R9.2 R14.2 R16.1 R17.1 R18.1 R19.1 R25.2 R28.2 R32.2 R53.2 R67.2 R70.2 R74.1 R76.1 R78.1 R80.1 R83.1 R84.1 R87.1 R88.1 R90.1 R94.1 R119.2 R123.2 R125.2 R129.2 R135.2 R138.2 SW2.1 SW2.3 SW3.1 SW3.3 SW4.1 SW4.3 U1.6 U2.4 U3.4 U4.A1 U4.A3 U4.B7 U4.C3 U4.D7 U4.E3 U4.J1 U5.4 U5.6 U6.1 U7.B3 U7.B5 U7.C1 U7.C5 U7.E5(VSSQ2) U8.A1 U8.A14 U8.B5 U8.B10 U8.E2 U8.E13 U8.G7 U8.G8 U8.H7 U8.H8 U8.J7 U8.J8 U8.K2 U8.K6 U8.K9 U8.K13 U8.L9 U8.N1 U8.N2 U8.N5 U8.N8 U8.P1 U8.P14 U9.1 U10.1 U10.4 U11.4 U12.2 U13.2 X2.2 X2.4
GND_EARTH: C115.1 J1.8 J1.9 J1.10 J1.11 J2.8 J2.9 J2.10 J2.11 J5.51 J5.52 J6.3 J6.4 J7.13 J7.14 MTG1.1(TP) MTG2.1(TP) MTG3.1(TP) MTG4.1(TP) R138.1
VDD_COIN_3V: D11.1 J3.18 J6.1 R64.1 TP4.1(TP)
VDD_HIGH_IN_3V3: C49.1 C50.1 C51.1 R71.2 R72.2 U8.P12
VDD_SNVS_3V3: C11.1 C103.1 D3.1 R20.1 R128.2 R130.2 U6.4(VCC)
VDD_SNVS_CAP: C54.1 C55.1 U8.M10
VDD_SNVS_IN: C60.1 R31.1 R91.1 R92.2 U8.M9
VDD_SOC_IN: C57.1 C58.1 C63.1 C65.1 C69.1 C75.1 C76.1 C77.1 C79.1 C81.1 C82.1 R107.1 U8.F6 U8.F7 U8.F8 U8.F9 U8.G6 U8.G9 U8.H6 U8.H9 U8.J5 U8.J9
VDD_USB_3V: C48.1 C59.1 U8.K8
VDDA_1V1_CAP: C52.1 C53.1 U8.P10
VDDA_2V5_CAP: C61.1 C62.1 U8.P8
VDDA_ADC_3V3: C28.1 C29.1 C30.1 R30.2 U8.N14
BOOT_MODE[0]: R19.2 SW1.4 U8.F11
BOOT_MODE[1]: R18.2 SW1.3 U8.G14
CAN2_RX: J3.15 U8.L10
CAN2_TX: J3.14 U8.H14
DBG_RESET: J4.18 R51.2
DBG_SWD_3V3: D5.2(C) J4.22
DBG_SWD_CLK: J4.19 R43.2
DBG_SWD_DIO: J4.20 R44.2
DBG_UART1_3V3: D6.2(C) J3.22
DBG_UART1_RXD: J3.19 R70.1 U10.2
DBG_UART1_TXD: J3.20 U10.3
DCDC_3V3: C4.1 C9.1 C10.1 C31.1 C32.1 C37.1 C39.1 C45.1 C46.1 C47.1 C56.1 C64.1 C94.1 C95.1 C105.1 D5.1 D6.1 FB4.1 FB5.1 FB6.1 J3.1 J4.1 L1.2 LED1.1 LED2.2 Q1.2(S) R2.1 R6.1 R7.1 R10.1 R21.1 R30.1 R39.1 R40.1 R41.1 R42.1 R45.1 R46.1 R49.1 R50.1 R52.1 R72.1 R73.1 R75.1 R77.1 R79.1 R81.1 R82.1 R85.1 R86.1 R89.1 R93.1 R97.1 R117.1 R121.1 R128.1 R133.1 R134.1 U5.5 U8.E6 U8.E9 U8.F5 U8.F10 U8.J10 U10.7 U10.8(VCC) U12.1 U12.3(S\H\D\N\)
DCDC_OUT: C19.1 C20.1 C84.1 L2.2 R107.2
ENET_CRS_DV: J3.5 U8.C12
ENET_MDC: J3.7 U8.A7
ENET_MDIO: J3.6 U8.C7
ENET_RXD0: J3.9 U8.E12
ENET_RXD1: J3.8 U8.D12
ENET_RXER: J3.4 U8.C13
ENET_TX_CLK: J3.13 U8.B13
ENET_TXD0: J3.11 U8.B12
ENET_TXD1: J3.10 U8.A12
ENET_TXEN: J3.12 U8.A13
FLASH_RST: R101.1 U8.C14
FLASH_VCC: C17.1 C18.1 C70.1 C73.1 C85.1 C87.1 C88.1 R23.1 R95.1 R99.1 R100.1 R102.1 R109.1 R117.2 R118.2 U7.B4 U7.D1 U7.E4 U8.K5(NVCC_SD1) U11.8
FLEXSPI_CLK: R96.1 R98.1 U8.L4
FLEXSPI_CLK_B: U7.B1 U8.P2
FLEXSPI_D0_A: R113.1 R114.2 U8.P3
FLEXSPI_D0_B: U7.D5 U8.M4
FLEXSPI_D1_A: R112.1 R116.2 U8.N4
FLEXSPI_D1_B: U7.E3 U8.M3
FLEXSPI_D2_A: R106.2 R108.1 U8.P4
FLEXSPI_D2_B: U7.E2 U8.M5
FLEXSPI_D3_A: R111.1 R115.2 U8.P5
FLEXSPI_D3_B: U7.E1 U8.L5
FLEXSPI_DQS: R110.1 U8.N3
FLEXSPI_SS0: R104.1 R105.1 R109.2 U8.L3
GPIO_AD_B1_04: J4.4 U8.L12
GPIO_AD_B1_05: J4.5 U8.K12
GPIO_AD_B1_06: J4.6 U8.J12
GPIO_AD_B1_07: J4.7 U8.K10
GPIO_AD_B1_08: J4.8 U8.H13
HF_CLK: R98.2 U7.B2
HF_D0_A: R113.2 U7.D3
HF_D1_A: R112.2 U7.D2
HF_D2_A: R108.2 U7.C4
HF_D3_A: R111.2 U7.D4
HF_DQS: R110.2 U7.C3
HF_RST: R100.2 R101.2 U7.A4
HF_SS0: R105.2 U7.C2
I2C1_SCL: J3.16 J5.42 R50.2 U8.J11
I2C1_SDA: J3.17 J5.43 R52.2 U8.K11
LCD_BL_PWM: R4.1 R55.1 U8.M11
LCD_CLK: C36.1 J5.32 R47.2
LCD_PWREN: Q1.1 R67.1 U8.L7
LCDIF_CLK: R47.1 U8.D7
LCDIF_D0: J5.4 R79.2 R80.2 U8.C8
LCDIF_D1: J5.5 R86.2 R87.2 U8.B8
LCDIF_D2: J5.6 R82.2 R83.2 U8.A8
LCDIF_D3: J5.7 R77.2 R78.2 U8.A9
LCDIF_D4: J5.8 R75.2 R76.2 U8.B9
LCDIF_D5: J5.12 R89.2 R90.2 U8.C9
LCDIF_D6: J5.13 R16.2 SW1.1 U8.D9
LCDIF_D7: J5.14 R73.2 R74.2 U8.A10
LCDIF_D8: J5.15 R85.2 R88.2 U8.C10
LCDIF_D9: J5.16 R17.2 SW1.2 U8.D10
LCDIF_D10: J5.17 R93.2 R94.2 U8.E10
LCDIF_D11: J5.22 R81.2 R84.2 U8.E11
LCDIF_D12: J5.23 U8.A11
LCDIF_D13: J5.24 U8.B11
LCDIF_D14: J5.25 U8.C11
LCDIF_D15: J5.26 U8.D11
LCDIF_ENABLE: J5.28 U8.E7
LCDIF_HSYNC: J5.29 U8.E8
LCDIF_VSYNC: J5.30 U8.D8
LDO_1V8: C90.1 C91.1 C92.1 R118.1 R122.1 U12.5
LDO_3V3: C102.1 C107.1 C110.1 R71.1 R120.1 R126.1 R130.1 U13.5
MCU_DCDC_IN_3V3: C74.1 C78.1 C80.1 C83.1 C86.1 C89.1 R103.2 R119.1 R120.2 R121.2 U8.K4 U8.L1 U8.L2
MCU_ONOFF: C34.1 R34.2 U8.M6
PMIC_ON_REQ: R11.1 R12.1 U8.K7
POR_B: C66.1 R24.2 R36.2 R51.1 R54.1 R91.2 U8.M7
POR_BUTTON: C15.1 D1.2(C) R11.2 R35.2
PWR_USB_OTG: R5.1 U1.5(OUTB)
QF_CLK: R96.2 U11.6
QF_D0_A: R114.1 U11.5
QF_D1_A: R116.1 U11.2
QF_D2_A: R23.2 R106.1 U11.3(W\P\_IO2)
QF_D3_A: R95.2 R115.1 U11.7
QF_SS0: R104.2 U11.1
SAI1_MCLK: J4.9 U8.M13
SAI1_RX_BCLK: J4.11 U8.J13
SAI1_RX_SYNC: J4.10 U8.L13
SAI1_RXD/AD1_Y-: J4.12 J5.37(Y-) U8.H12
SAI1_TX_BCLK/AD3_X-: J4.14 J5.35 U8.G12
SAI1_TX_SYNC/AD4_X+: J4.15 J5.34 U8.J14
SAI1_TXD/AD2_Y+: J4.13 J5.36 U8.H11
SD1_CLK: C116.1 R63.1 U8.J3
SD1_CMD: R56.1 U8.J4
SD1_D0: R66.1 U8.J1
SD1_D1: R69.1 U8.K1
SD1_D2: R60.1 U8.H2
SD1_D3: R58.1 U8.J2
SD_CD: D4.1 J7.10 R37.2 R38.2
SD_CD_SW: R38.1 U8.D13
SD_CLK: C44.1 D10.1 J7.5 R62.2 R63.2
SD_CMD: D7.1 J7.3 R56.2 R57.2
SD_DAT0: D12.1 J7.7 R65.2 R66.2
SD_DAT1: D13.1 J7.8 R68.2 R69.2
SD_DAT2: D9.1 J7.1 R60.2 R61.2
SD_DAT3: D8.1 J7.2 R58.2 R59.2
SDRAM_3V3: C13.1 C14.1 C93.1 C96.1 C97.1 C98.1 C100.1 C104.1 C106.1 FB6.2 R127.1 U4.A7 U4.A9 U4.B3 U4.C7 U4.D3 U4.E7 U4.J9
SDRAM_CLK: R15.2 U4.F2
SEMC_A0: U4.H7 U8.C2
SEMC_A1: U4.H8 U8.G1
SEMC_A2: U4.J8 U8.G3
SEMC_A3: U4.J7 U8.H1
SEMC_A4: U4.J3 U8.A6
SEMC_A5: U4.J2 U8.B6
SEMC_A6: U4.H3 U8.B1
SEMC_A7: U4.H2 U8.A5
SEMC_A8: U4.H1 U8.A4
SEMC_A9: U4.G3 U8.B2
SEMC_A10: U4.H9 U8.G2
SEMC_A11: U4.G2 U8.B4
SEMC_A12: U4.G1 U8.A3
SEMC_BA0: U4.G7 U8.C1
SEMC_BA1: U4.G8 U8.F1
SEMC_CAS: U4.F7 U8.D3
SEMC_CKE: R129.1 U4.F3 U8.A2
SEMC_CLK: R15.1 U8.B3
SEMC_CS0: R127.2 U4.G9 U8.E1
SEMC_D0: U4.A8 U8.E3
SEMC_D1: U4.B9 U8.F3
SEMC_D2: U4.B8 U8.F4
SEMC_D3: U4.C9 U8.G4
SEMC_D4: U4.C8 U8.F2
SEMC_D5: U4.D9 U8.G5
SEMC_D6: U4.D8 U8.H5
SEMC_D7: U4.E9 U8.H4
SEMC_D8: U4.E1 U8.C6
SEMC_D9: U4.D2 U8.C5
SEMC_D10: U4.D1 U8.D5
SEMC_D11: U4.C2 U8.C4
SEMC_D12: U4.C1 U8.D4
SEMC_D13: U4.B2 U8.E5
SEMC_D14: U4.B1 U8.C3
SEMC_D15: U4.A2 U8.E4
SEMC_DM0: U4.E8 U8.H3
SEMC_DM1: U4.F1 U8.D6
SEMC_DQS: C22.1 U8.B7
SEMC_RAS: U4.F8 U8.D2
SEMC_WE: U4.F9(W\E\) U8.D1
SPDIF_IN: J4.17 U8.M12
SPDIF_OUT: J4.16 U8.L11
SWD_CLK: R32.1 R43.1 U8.F12
SWD_DIO: R44.1 R49.2 U8.E14
UART1_RXD: R46.2 U8.L14 U10.6
UART1_TXD: R45.2 U8.K14 U10.5
USB1_GND: FB7.2 J2.5
USB2_GND: FB8.2 J1.5
USB_HOST_DN: J1.2 L3.2 R131.2 U2.2
USB_HOST_DP: J1.3 L3.3 R132.2 U2.1
USB_HOST_OC: R6.2 U1.2 U8.M14
USB_HOST_PWR: R7.2 R135.1 U1.1 U8.B14
USB_OTG1_DN: L4.1 R136.1 U8.M8
USB_OTG1_DP: L4.4 R137.1 U8.L8
USB_OTG1_ID: J2.4 Q2.1 R134.2 U3.3 U8.H10
USB_OTG1_OC: R133.2 U1.3 U8.G11
USB_OTG2_DN: L3.1 R131.1 U8.N7
USB_OTG2_DP: L3.4 R132.1 U8.P7
USB_OTG_DN: J2.2 L4.2 R136.2 U3.2
USB_OTG_DP: J2.3 L4.3 R137.2 U3.1
USER_BUTTON: C33.1 R31.2 R33.2 U8.L6
USER_LED_B: R48.2 U8.G10
USER_LED_G: R29.2 U8.G13
USER_LED_R: R27.2 U8.F14
WDOG_B: C16.1 U8.D14
N1426169: D3.2(C) D11.2(C) R64.2 R92.1
N1428044: C24.1 R20.2 R21.2 R22.1 U9.3(VCC)
N1428076: R22.2 R24.1 U9.2
N1428666: C26.1 R25.1 R26.1 U8.P11 X2.3
N1428682: L2.1 U8.M1 U8.M2
N1428736: C27.1 R26.2 U8.N11 X2.1
N1428810: C25.1 U8.N9 X1.1
N1428818: C71.1 R103.1 U8.K3
N1428874: C23.1 U8.P9 X1.2
N1430764: C6.1 C7.1 C8.1 R8.2 R124.1 U5.2(VIN)
N1430772: L1.1 U5.3
N1431030: R9.1 R10.2 U5.7
N1431040: C12.1 R12.2 R13.2 R124.2 U5.8 U6.2
N1431138: C101.1 TP3.1(TP) U5.1
N1431606: C16.2 D2.2(C) R14.1
N1435220: C67.1 C72.1 R97.2 U8.J6
N1441990: TP1.1(TP) U8.N12
N1446802: R102.2 U7.A5
N1446884: R99.2 U7.A2
N1454429: Q2.3 R2.2 R3.1 R4.2 U1.4
N1538445: R39.2 SW1.8
N1538449: R40.2 SW1.7
N1538453: R41.2 SW1.6
N1538457: R42.2 SW1.5(B4)
N1582760: R34.1 SW4.2 SW4.4(B2)
N1582904: C35.1 R35.1 R36.1 SW3.2 SW3.4(B2)
N1658417: R33.1 SW2.2 SW2.4(B2)
N1660774: R28.1 U8.F13
N1700883: LED1.2(C) R1.2
N1720722: LED2.1(RED) R27.1
N1720728: LED2.3 R48.1
N1720734: LED2.4 R29.1
N1744694: J5.49 R54.2
N1744704: J5.50 R53.1 R55.2
N1790471: D1.1 D2.1 R13.1 U6.3
N1791257: TP2.1(TP) U8.N10
N1827694: C102.2 R125.1 R126.2 U13.4
N1830761: C92.2 R122.2 R123.1 U12.4

Pads without a net: J1 4 6 7; J2 6 7; J5 38 39 40 41; J7 11 12 15 16; U2 3 5; U3 5; U4 E2; U7 A3; U8 N13 P13

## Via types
v1: diameter 0.356, hole 0.203, TOP to BOTTOM, 143 vias
v2: diameter 0.457, hole 0.203, TOP to BOTTOM, 406 vias
v3: diameter 0.406, hole 0.203, TOP to BOTTOM, 2 vias

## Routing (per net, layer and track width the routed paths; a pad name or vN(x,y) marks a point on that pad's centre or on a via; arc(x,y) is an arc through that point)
3V3_LCD: length 4.5
  BOTTOM w0.889: Q1.3 57.81,31.01 57.81,30.19 58.77,29.24 59.99,29.24 v2(60.22,29.47)
  vias: v2(59.76,29.04)
3V3_SD: length 61.6
  TOP w0.203: v2(58.01,27.48) 57.68,27.81 51.84,27.81 51.44,28.22 49.86,28.22 49.65,28.02 R37.1
  LYR03 w0.381: v2(65.43,32.26) 63.61,32.26 v2(63.3,32.58) 63.26,32.62 60.2,32.62 59.99,32.82 v2(59.99,32.82) ; v2(59.66,10.83) 58,12.5 v2(57.81,12.5)
  PWR04 w0.381: v2(59.66,10.83) 62.23,13.4 62.23,31.51 v2(63.3,32.58)
  BOTTOM w0.254: v2(59.66,10.83) 59.66,11.23 59.69,11.25 R62.1
  BOTTOM w0.381: v2(58.01,27.48) 64.59,27.48 65.29,28.18 J7.4 65.29,31.38 C43.1 65.33,32.16 v2(65.43,32.26) 65.57,32.4 C42.1 65.57,33.52 64.49,34.6 61.79,34.6 FB5.2 ; R65.1 58.09,12.22 v2(57.81,12.5) 57.53,12.22 R68.1 ; R59.1 63.04,32.32 v2(63.3,32.58) 63.3,32.56 63.32,32.56 63.57,32.32 R57.1 ; v2(59.99,32.82) 59.99,32.82 60.49,32.32 R61.1
5V_HOST: length 0.5
  TOP w0.305: U2.6 6.98,31.22
5V_OTG: length 8.9
  TOP w0.508: 11.71,36.6 11.71,37.14 12.35,37.78 J3.3 12.49,37.78 12.85,37.42 12.85,36.57 12.83,36.55
  PWR04 w0.508: 11.71,36.53 11.71,37.14 12.35,37.78 J3.3 12.41,37.78 12.8,37.39 12.8,36.63 12.85,36.58 ; 13.44,3.28 12.41,2.25 J4.3 11.84,2.79 11.84,3.48
  vias: v2(6.17,11.51) v2(6.65,12.04) v2(6.65,11.51) v2(11.13,35.59) v2(11.71,35.56) v2(15.77,4.29) v2(16.28,4.29)
5V_USB_HOST: length 39.7
  TOP w0.203: U8.P6 39.14,16.53
  TOP w0.305: v2(38.35,14.41) C21.1 38.89,16.28 39.14,16.53
  LYR03 w0.381: v2(38.35,14.41) 32.64,14.41 32.49,14.56 29.41,14.56 27.56,12.7 22.89,12.7 21.66,13.93 13.65,13.93 12.7,12.98 10.19,12.98 8.31,14.86 v2(8.31,17.86)
  BOTTOM w0.381: C112.1 8.79,17.38 v2(8.31,17.86)
  vias: v2(8.71,20.18) v2(9.24,20.18)
5V_USB_OTG: length 117.3
  TOP w0.203: U8.N6 v1(39.07,17.12)
  TOP w0.381: R5.2 3.95,20.45
  TOP w0.508: 3.95,20.45 6.31,20.45 7.51,19.26 U1.7
  LYR03 w0.305: v1(39.07,17.12) 39.07,16.94 38.77,16.64 37.49,16.64 35.99,18.14 ; v2(12.34,14.23) 12.34,13.92 12.04,13.62 10.49,13.62 9.68,14.43 v2(9.68,15.39)
  LYR03 w0.381: 35.99,18.14 33.93,20.19 29.57,20.19 25.91,16.54 10.99,16.54 v2(10.15,17.38)
  LYR03 w0.508: v1(55.8,30.71) 55.7,30.81 55.7,31.19 ; 55.7,31.19 55.7,32.03 52.91,34.82 49.91,34.82 48.54,36.2 v2(46.28,36.2) v2(45.75,36.2) ; 55.7,31.19 v1(55.45,30.94)
  PWR04 w0.508: v2(46.28,36.2) v2(45.75,36.2) 44.48,34.93 6.22,34.93 5.35,34.06 5.35,20.2 7.38,18.18
  BOTTOM w0.305: v1(39.07,17.12) 38.81,16.85 C68.1 ; U13.3 12.61,13.78 12.34,14.05 v2(12.34,14.23)
  BOTTOM w0.381: C113.1 7.87,17.1 7.87,17.32 v2(7.54,17.65) ; C114.1 7.01,17.42 7,17.43 7,17.57 v2(6.91,17.65)
  vias: v2(9.68,16.03)
GND: length 294.1
  TOP w0.203: U8.N5 v1(38.42,17.12) ; U8.N8 v1(40.37,17.77) ; U8.N2 U8.N1 ; U8.P14 v1(44.92,16.47) ; U8.K2 v1(36.47,19.07) ; U8.A14 v1(44.92,24.92) ; U8.K13 v1(44.27,19.07)
  TOP w0.254: C25.2 43.47,14.16 v2(43.71,13.92) ; J5.21 63.12,17.71 63.29,17.54 63.31,17.54 v2(63.45,17.4) 63.26,17.21 J5.20 ; R3.2 v2(2.26,22.33) 2.26,19.38 R1.1 ; SW4.1 SW4.3 51.14,9.41 ; U4.E3 v2(16.01,25.56) ; U4.A3 v2(19.21,25.56) ; R17.1 38.25,32.16 v2(38.2,32.21) ; R17.1 R18.1 ; R17.1 R16.1 ; v2(40.41,29.36) 40.18,29.59 39.16,29.59 38.91,29.85 R19.1 ; v2(49.09,26.38) 49.09,26.57 49.34,26.82 D4.2 ; U4.D7 v2(16.81,21.56) ; 53.47,19.57 53.52,19.62 53.52,22.02 52.93,22.61 R28.2 ; 53.47,19.57 SW2.1 ; 53.47,19.57 SW2.3 50.53,19.57 50.44,19.48 50.29,19.48 ; U8.K6 v1(39.72,19.72) U8.J7 ; U8.E2 v1(36.47,22.32) ; U8.N1 v1(35.82,17.12) 36.15,16.79 U8.P1 ; 50.29,19.48 50.29,19.33 49.89,18.93 C33.2 ; 50.29,19.48 50.24,19.43 ; v2(63.46,20.53) 63.28,20.71 J5.27 ; U8.E13 v1(44.27,22.97) ; R9.2 20.62,11.33 20.78,11.18 20.98,11.18 v2(21.03,11.13) ; X2.2 44.26,12 44.04,11.79 ; 48.51,10.11 48.47,10.15 X2.4 ; U4.C3 v2(17.61,25.56) ; v2(63.43,23.85) 63.28,23.71 J5.33 ; C17.2 25.73,8.96 ; 25.73,8.96 25.58,8.96 v2(25.58,8.96) ; 25.73,8.96 C18.2 ; C15.2 22.06,9.11 v2(21.95,9.22) ; J5.31 63.15,22.71 v2(63.45,22.4) ; J5.18 63.17,16.21 63.45,16.49 v2(63.45,16.71) 63.45,16.71 J5.19 ; U8.G7 v1(39.72,21.67) ; U8.H8 v1(40.37,20.37) U8.J8 ; U8.B10 v1(42.32,24.92) ; 10.63,28.74 v2(10.63,23.94) v2(10.63,21.4) v2(10.63,19.86) 10.63,16.7 ; U8.A1 v1(35.82,25.57) ; 50.24,19.43 v2(50.25,19.43) ; 50.24,19.43 50.19,19.48 50.12,19.48 49.86,19.74 C32.2 ; U8.B5 v1(38.42,24.92) ; C28.2 C29.2 C30.2 48.14,16.36 49,15.5 ; C31.2 v2(49.15,21.39) ; v2(30.21,19.11) v2(29.58,18.48) v2(28.82,17.71) v2(28.05,16.95) 24.5,13.4 ; 38.52,28.71 C22.2 ; U4.B7 v2(18.41,22.36) ; U4.J1 v2(12.01,27.16) ; U8.G8 v1(41.02,21.67) ; R14.2 23.58,9.16 23.32,9.42 23.32,10.64 v2(23.22,10.75) ; U8.H7 v1(39.72,20.37) ; U8.L9 41.35,18.74 v1(41.67,19.07) U8.K9 ; U4.A1 v2(19.21,27.16)
  TOP w0.305: v2(43.71,13.92) 44.06,13.92 R25.2 ; J5.9 63.57,11.71 v2(63.7,11.84) ; 39.35,13.64 C21.2 ; 39.35,13.64 39.52,13.64 39.55,13.61 ; 39.35,13.64 39.55,13.44 ; v2(29.13,7.11) 29.13,7.85 U7.E5 ; v2(43.86,15.34) 43.86,15.34 43.86,15.32 44.32,14.86 44.32,14.82 44.32,14.82 44.32,14.19 R25.2 ; R53.2 v2(57.23,33.68) ; v1(31.19,12.77) 31.19,12.79 31.2,12.79 31.42,12.57 U7.C1 ; C26.2 44.35,13.26 44.32,13.23 ; SW4.1 55.25,9.41 56.26,10.42 v2(56.26,10.62) ; R25.2 44.32,13.23 ; v1(44.92,16.47) 44.98,16.41 44.98,16.11 45.62,15.47 v2(46.23,15.47) 47.09,14.61 47.09,13.47 C27.2 47.58,12.98 48.21,12.98 48.51,12.68 48.51,9.5 48.21,9.2 44.35,9.2 44.04,9.5 44.04,11.79 ; 44.04,11.79 44.04,12.96 v2(44.27,13.18) 44.32,13.23 ; 44.04,11.79 43.94,11.69 41.88,11.69 v2(41.86,11.71) 41.83,11.69 39.84,11.69 39.59,11.94 39.59,12 39.55,12.04 39.55,13.44 ; J5.2 61.36,8.21 v2(61.21,8.36) 61.21,8.4 61.24,8.43 61.24,8.48 61.41,8.64 61.45,8.64 61.52,8.71 J5.3 ; U7.C5 31.95,8.66 v2(32.03,8.66) 32.42,8.27 U7.B5 ; 51.14,9.41 50.25,9.41 49.94,9.1 C34.2 ; v2(60.35,7.37) 60.69,7.71 J5.1 ; R32.2 v2(49.12,5.16) ; 39.55,13.61 39.88,13.94 40,13.94 v2(40.16,14.1) 40.25,14.1 40.31,14.16 C23.2 ; 39.55,13.61 39.55,13.44 ; J5.44 63.3,29.21 v2(63.6,28.91) ; 59.06,30.25 59.06,30.25 v2(59.08,30.25) ; 59.06,30.25 59.03,30.28 59.01,30.25 57.12,30.25 56.94,30.08 C39.2 ; 59.06,30.25 C41.2 ; U7.B3 32.61,10.14 v1(32.99,10.52) ; R9.2 C12.2 ; J5.10 63.14,12.21 v2(63.65,12.71) J5.11 ; C22.2 v2(38.9,28.18)
  TOP w0.381: 40.91,11.69 40.93,11.67 U9.1 ; C11.2 18.28,6.83 U6.1 18.8,4.93 17.53,3.66 11.31,3.66 J4.2 ; 49.21,15.28 50.33,15.28 51.12,14.49 SW3.3 SW3.1 55.08,15.15 v2(56.21,16.28) ; 49.21,15.28 C35.2 ; 49.21,15.28 49,15.5 ; v2(42.16,6.87) 42.16,6.88 41.88,7.16 C24.2 ; C40.2 58.95,31.8 v2(58.85,31.9) 56.55,31.9 C38.2 ; C36.2 55.02,24.92 C37.2 55.55,24.87 v2(55.85,25.17) ; C13.2 19.62,25.97 v2(19.21,25.56)
  TOP w0.508: 9.25,36.37 9.25,37.16 9.86,37.78 J3.2 9.87,37.78 10.41,37.24 10.41,36.53
  GND02 w0.508: J3.21 58.92,36.99 ; J3.21 57.34,36.99 ; J3.21 57.34,38.57 ; J3.21 58.92,38.57 ; J3.2 10.66,38.57 ; J3.2 9.08,36.99 ; J3.2 10.66,36.99 ; J3.2 9.08,38.57 ; 57.34,3.01 J4.21 ; J4.21 58.92,1.43 ; J4.21 57.34,1.43 ; J4.21 58.92,3.01 ; J4.2 10.66,1.43 ; J4.2 9.08,1.43 ; J4.2 10.66,3.01 ; J4.2 9.08,3.01
  GND05 w0.102: 41.99,18.09 42,18.09
  GND05 w0.508: J4.21 58.92,1.43 ; J4.21 58.92,3.01 ; J4.21 57.34,3.01 ; J4.21 57.34,1.43 ; 9.08,1.43 J4.2 ; J4.2 10.66,1.43 ; J4.2 9.08,3.01 ; J4.2 10.66,3.01 ; 9.08,36.99 J3.2 ; J3.2 10.66,38.57 ; J3.2 9.08,38.57 ; J3.2 10.66,36.99 ; J3.21 58.92,38.57 ; J3.21 57.34,36.99 ; J3.21 58.92,36.99 ; J3.21 57.34,38.57
  BOTTOM w0.102: C64.2 40.36,24.23 39.98,24.61 39.98,24.92 39.73,25.17 39.73,26.35 ; C69.2 38.42,22.39 38.75,22.72 U8.B5 v1(38.42,24.92)
  BOTTOM w0.203: C93.2 18.15,23.05 ; v1(39.72,19.72) 39.21,19.2 C67.2 ; 14.58,12.45 14.78,12.24
  BOTTOM w0.254: U10.1 54.28,33.29 54.53,33.54 54.53,34.06 v2(54.51,34.09) ; R76.1 45.73,29.44 v2(45.44,29.15) ; R76.1 R78.1 R80.1 R83.1 R87.1 ; R76.1 R74.1 ; v2(7.14,22.28) 7.39,22.53 R135.2 ; v2(24.05,6.55) 24.28,6.78 C87.2 ; C81.2 32.97,13.69 v2(32.94,13.69) ; 39.73,26.35 39.73,26.47 39.8,26.54 v2(39.78,26.54) ; v1(36.47,19.07) 36.43,19.11 C74.2 ; U10.4 53.21,31.79 52.43,31 v2(52.43,30.89) ; 18.15,23.05 18.15,22.62 v2(18.41,22.36) ; R94.1 R90.1 39.75,30.02 v2(40.41,29.36) ; D10.2 C44.2 ; D13.2 D12.2
  BOTTOM w0.305: C50.2 45.31,16.08 v1(44.92,16.47) 44.54,16.08 C51.2 44.27,15.64 ; C50.2 45.47,15.67 ; C50.2 C49.2 v2(46.23,15.47) ; v2(19.94,13.23) 19.89,13.23 19.58,12.93 R123.2 ; C56.2 41.31,21.67 v1(41.02,21.67) 40.87,21.67 40.63,21.9 C63.2 ; v2(40.16,14.1) 40.25,14.1 40.31,14.16 C62.2 C61.2 40.31,16.36 ; v2(38.9,28.18) 38.47,28.18 36.14,30.51 36.14,31.09 v2(35.93,31.3) 36.14,31.52 C72.2 ; C71.2 36.13,17.03 36.02,16.92 ; v1(42.32,24.92) 42.24,25 42.24,26.84 R88.1 R84.1 ; C59.2 41.02,18.32 C54.2 41.73,19.01 v1(41.67,19.07) ; C52.2 43.46,15.73 v2(43.86,15.34) ; C68.2 38.96,15.85 39.52,16.41 39.57,16.41 39.6,16.43 C66.2 39.7,16.43 39.73,16.41 40.26,16.41 40.31,16.36 ; v2(14.21,24.32) 13.71,24.82 R129.2 ; 36.02,16.92 v1(35.82,17.12) ; 36.02,16.92 C76.2 36.04,16.59 C75.2 ; v2(16.81,21.56) 16.75,21.61 C98.2 ; 40.31,16.36 C60.2 40.31,17.7 v1(40.37,17.77) ; C81.2 C79.2 C77.2 ; v2(12.05,22.57) C104.2 11.74,23.17 v2(11.46,22.89) ; C100.2 15.99,25.57 v2(16.01,25.56) ; C106.2 11.44,21.78 v1(11.43,21.77) ; U12.2 21.49,6.23 v2(21.43,6.17) ; C47.2 v2(47.42,24.28) 47.22,24.09 C48.2 ; R125.2 15.09,11.94 14.78,12.24
  BOTTOM w0.33: v2(18.41,22.36) 18.4,22.35 C96.2 ; v2(17.61,25.56) 17.64,25.52 C97.2
  BOTTOM w0.381: v2(53.09,18.31) 53.2,18.43 J7.9 ; 8.79,15.67 C112.2 C113.2 ; C42.2 66.77,32.84 66.42,32.49 v2(66.42,32.46) ; R70.2 v2(54.84,35.56) ; v2(7.01,15.65) C114.2 7.04,16.31 C113.2 ; C113.2 7.9,15.7 ; D9.2 60.5,30.46 v2(60.43,30.38) ; J7.6 64.59,16.28 v2(65.51,17.2) ; v2(64.03,30.89) 63.83,31.09 D7.2 D8.2 ; C116.2 v2(58.16,9.5) ; C45.2 58.62,35.18 v2(58.9,35.46) ; v2(57.23,33.68) 57.23,34.39 57.38,34.54 R67.2 ; C70.2 v2(37.01,9.7) C73.2 ; v2(59.84,13.74) 59.84,13.72 59.69,13.57 D10.2 ; v2(28.4,7.19) 28.4,7.32 27.96,7.75 C85.2 ; C46.2 53.14,35.48 v2(53.04,35.59) ; U11.4 45.59,6.55 v2(45.39,6.35) ; v2(63.98,8.51) 63.44,9.05 J6.2 ; C43.2 v2(66.1,32.03) ; D12.2 v2(58.17,13.69)
  BOTTOM w0.508: v2(7.14,22.28) 7.1,22.24 Q2.2 5.95,21.5 ; 10.62,3.48 10.6,3.47 10.6,2.92 9.9,2.22 J4.2 9.83,2.22 9.32,2.73 9.32,3.38 9.33,3.39
  vias: v2(4.78,14.71) v2(5.44,14.71) v2(7.19,21.49) v2(8.03,27.51) v2(8.02,27) v2(8.26,31.93) v2(8.26,31.42) v2(8.39,7.71) v2(8.56,27.48) v2(8.56,27) v2(8.56,12.07) v2(8.56,11.43) v2(8.76,31.93) v2(8.76,31.42) v2(9.04,33.91) v2(9.25,7.05) v2(9.26,8.28) v2(9.27,7.65) v2(9.88,6.07) v2(10.08,33.52) v2(10.52,6.07) v2(11.01,29.12) v2(11.18,6.07) v2(11.61,14.23) v2(11.8,29.91) v2(12.09,14.96) v2(13.07,31.18) v2(13.05,14.29) v2(14.07,13.21) v2(16.48,10.62) v2(16.48,10.01) v2(16.99,10.62) v2(16.99,10.03) v2(17.5,8.33) v2(20.7,13.23) v2(20.78,19.43) v2(21.2,32.19) v2(21.45,19.43) v2(23.1,32.19) v2(23.11,13.29) v2(23.37,15.83) v2(23.6,13.29) v2(23.98,15.8) v2(24.08,13.29) v2(25.01,32.19) v2(26.91,32.19) v2(28.82,32.19) v2(29.95,15.5) v2(30.47,32.19) v2(31.34,16.94) v2(32.37,32.19) v2(34.28,32.19)
GND_EARTH: length 98.4
  TOP w0.102: J1.8 1.81,33.53 1.86,33.48 ; J2.9 1.7,6.48 1.74,6.52 ; J2.8 1.63,13.72 ; J1.9 1.7,26.29
  TOP w0.381: 2.82,2.87 MTG2.1 ; 2.82,2.87 2.82,3.48 ; 2.82,2.87 4.37,4.42 ; MTG2.1 4.24,2.52 5.18,3.46 ; MTG2.1 2.29,2.52 0.81,3.99 ; MTG1.1 3.75,37.48 5.28,39.02 ; MTG1.1 2.82,37.26 ; MTG1.1 2.82,38.36 3.99,39.52 ; 2.82,37.21 2.82,35.1 2.84,35.08 ; 2.82,37.21 2.82,37.26 ; 2.82,37.21 1.07,35.46 ; 2.82,37.26 4.55,35.54 ; 63.22,35.71 64.99,37.48 ; 64.99,37.48 64.57,37.48 63.14,38.91 ; 64.99,37.48 MTG3.1 65.18,37.28 66.98,35.49 ; J5.51 65.18,5.79 65.18,2.55 ; 62.71,2.52 MTG4.1 65.18,2.55 ; 67.08,4.45 65.18,2.55 ; 1.65,4.65 2.82,3.48 ; 2.82,3.48 2.82,4.9 2.92,5.01
  TOP w0.508: 1.44,13.68 1.44,14.67 1.45,14.68 ; 1.44,13.68 0.53,14.58 ; 1.44,13.68 1.44,13.67 1.58,13.67 2.44,14.53 ; 1.44,6.37 1.44,5.5 1.42,5.49 ; 1.44,6.37 1.44,6.52 1.74,6.52 2.54,5.72 ; 1.44,6.37 0.64,5.56 ; J5.52 65.07,33.91 65.96,34.8 ; J5.52 64.92,33.91 63.53,35.31 ; J5.52 64.96,37.27 MTG3.1 ; 1.44,26.33 1.44,25.42 1.42,25.4 ; 1.44,26.33 1.26,26.33 0.53,25.6 ; 1.44,26.33 1.66,26.33 2.41,25.58 ; 1.44,33.48 1.39,33.48 0.61,34.27 ; 1.44,33.48 1.86,33.48 2.62,34.24 ; 1.44,33.48 1.44,34.51 1.42,34.52 ; 66.62,6.05 66.59,6.01 J5.51 64.6,6.01 63.55,4.95
  BOTTOM w0.381: 1.41,27.33 1.41,26.36 1.44,26.33 ; 0.53,34.39 1.44,33.49 ; 1.44,33.49 1.44,33.48 ; 1.44,33.49 1.44,34.46 1.45,34.47 ; 1.68,33.48 1.78,33.48 2.62,32.64 ; 1.68,33.48 2.57,34.37 ; 1.68,33.48 1.44,33.48 ; 1.44,6.44 1.44,6.52 ; 1.44,6.44 0.53,5.54 ; 1.44,6.44 1.44,5.53 1.42,5.51 ; 1.44,6.52 1.53,6.52 ; 1.44,6.52 1.41,6.55 1.41,7.47 ; 1.44,6.52 1.43,6.52 0.53,7.42 ; 1.44,33.48 1.41,33.45 1.41,32.56 ; 1.44,33.48 1.35,33.48 0.48,32.62 ; 67.02,15.34 67.51,15.34 67.54,15.32 ; 1.53,6.52 2.36,5.69 ; 1.53,6.52 1.7,6.52 2.5,7.32 ; 0.48,27.26 1.41,26.33 1.44,26.33 ; v2(67.36,14.56) 67.36,14.61 67.29,14.61 J7.14 ; 1.44,26.31 1.44,25.19 1.42,25.17 ; 1.44,26.31 0.56,25.43 ; 1.44,26.31 1.44,26.33 ; 1.4,13.67 1.44,13.67 ; 1.4,13.67 1.32,13.67 0.48,14.5 ; 1.4,13.67 0.51,12.78 ; 1.44,13.67 1.44,14.59 1.42,14.61 ; 1.44,13.67 1.41,13.64 1.41,12.7 ; 1.44,13.67 1.5,13.67 ; 1.66,26.33 1.73,26.33 2.5,27.11 ; 1.66,26.33 2.41,25.58 ; 1.66,26.33 1.44,26.33 ; 67.29,29.74 67.48,29.74 v2(67.49,29.74) ; 1.5,13.67 2.34,14.5 ; 1.5,13.67 1.72,13.67 2.51,12.88
  BOTTOM w0.889: 67.29,29.74 J7.13 ; J7.14 67.02,15.34
  vias: v2(0.57,31.11) v2(0.56,28.71) v2(0.65,11.29) v2(0.66,8.89) v2(0.81,21.19) v2(0.81,20.25) v2(0.76,18.9) v2(1.96,32.41) v2(1.96,27.33) v2(1.96,12.62) v2(1.96,7.55) v2(66.57,34.7)
VDD_COIN_3V: length 47.4
  PWR04 w0.381: v2(60.59,9.27) 62.92,11.6 62.92,23.63 62.91,23.64 62.91,30.85 63.88,31.83 63.88,33.05 60.55,36.39 51.9,36.39 J3.18
  BOTTOM w0.381: J6.1 61.58,10.3 60.59,9.31 v2(60.59,9.27) 60.59,8.85 D11.1 59.44,7.69 R64.1 59.44,5.03 TP4.1
VDD_HIGH_IN_3V3: length 5
  TOP w0.203: U8.P12 v1(43.62,16.47)
  BOTTOM w0.305: R71.2 R72.2 C49.1 C50.1 45.29,16.84 45.19,16.94 44.37,16.94 C51.1 44.05,16.84 43.67,16.47 v1(43.62,16.47)
VDD_SNVS_3V3: length 39.6
  TOP w0.305: U6.4 18.58,8.52 17.65,7.6 C11.1 16.79,8 v2(16.79,8.3)
  TOP w0.381: D3.1 38.89,7.77 39.37,7.29 R20.1 39.88,6.88 40.4,6.36 v2(41.11,6.36)
  LYR03 w0.305: v2(16.79,8.3) 19.46,5.64 v2(19.46,5.13)
  PWR04 w0.508: v2(19.46,5.13) 20.32,4.27 27.08,4.27 27.81,3.53 38.28,3.53 v2(41.11,6.36)
  BOTTOM w0.305: R130.2 12.34,7.83 R128.2 C103.1 14.76,8.1 16.59,8.1 v2(16.79,8.3)
VDD_SNVS_CAP: length 2.9
  TOP w0.203: U8.M10 v1(42.32,17.77)
  BOTTOM w0.305: v1(42.32,17.77) 41.95,17.77 C54.1 41.73,16.03 C55.1
VDD_SNVS_IN: length 21.4
  TOP w0.203: U8.M9 v1(41.02,17.77)
  TOP w0.305: R31.1 50.25,16.42 v2(50.25,16.07)
  LYR03 w0.305: v2(39.55,14.4) 39.7,14.56 39.9,14.56 40.59,15.24 40.59,17.33 v1(41.02,17.77)
  PWR04 w0.305: v2(39.55,14.4) 39.55,13.77 40.67,12.65 48.42,12.65 50.25,14.49 v2(50.25,16.07)
  BOTTOM w0.305: v1(41.02,17.77) 41.07,17.72 C60.1
  BOTTOM w0.381: v2(39.55,14.4) R91.1 R92.2
VDD_SOC_IN: length 21.5
  TOP w0.254: U8.H6 v1(39.07,21.02) U8.G6 v1(39.07,21.67) U8.F6 v1(39.72,22.32) U8.F7 U8.F8 v1(41.02,22.32) U8.F9 41.49,21.85 41.49,21.49 U8.G9 41.67,21.02 U8.H9 ; U8.H9 v1(41.02,20.37) U8.J9 v1(41.67,20.37) U8.H9 ; U8.J5 v1(38.42,19.72)
  PWR04 w0.102: 36.91,20.04 36.99,20.04 36.99,20.04 37.26,20.04 37.26,20.04 37.44,20.04 ; 37.45,21.99 37.99,21.99 ; 37.45,21.99 37.44,22 ; 37.45,21.99 37.45,21.99 37.45,21.53 37.47,21.52 ; 36.8,22.1 36.8,22.11 36.8,22.61 36.83,22.64 ; 38.07,19.48 37.98,19.39 37.44,19.39 ; 37.41,22.64 36.83,22.64 ; 37.41,22.64 37.96,22.64 ; 37.41,22.64 37.45,22.61 37.45,22.01 37.44,22 ; 36.83,22.64 36.28,22.64 36.27,22.63 ; 37.44,22 37.43,21.99 36.98,21.99 36.96,21.97 ; 37.44,20.04 37.45,20.05 37.45,20.52 37.44,20.52 37.47,20.55 ; 37.44,20.04 37.64,20.04 37.64,20.04 37.91,20.04 37.91,20.04 37.95,20.04 ; 37.44,20.04 37.45,20.03 37.45,19.4 37.44,19.39 ; 40.05,20.04 40.05,20.5 40.06,20.51 40.06,20.52 ; 40.05,20.04 40.05,20.04 39.57,20.04 39.57,20.04 ; 40.05,20.04 40.05,20.04 40.54,20.04 40.54,20.04 ; 40.05,20.04 40.05,19.85 40.05,19.85 40.05,19.4 40.06,19.39 ; 36.93,19.41 36.95,19.39 37.44,19.39 ; 38.13,20.58 38.1,20.55 38.1,20.5 38.1,20.5 38.1,20.23 38.1,20.23 38.1,20.19 ; 38.76,20.17 38.75,20.18 38.75,20.5 ; 39.5,19.41 39.51,19.39 39.86,19.39 40.06,19.39 ; 40.51,19.39 40.06,19.39 ; 39.42,20.17 39.4,20.19 39.4,20.5 ; 38.61,20.68 38.59,20.69 38.29,20.69
  BOTTOM w0.305: v1(39.72,22.32) 40.07,22.66 40.37,22.66
  vias: v2(34.24,16.74) v2(34.24,16.21) v2(34.24,15.67) v2(34.8,16.74) v2(34.8,16.21) v2(34.8,15.67)
